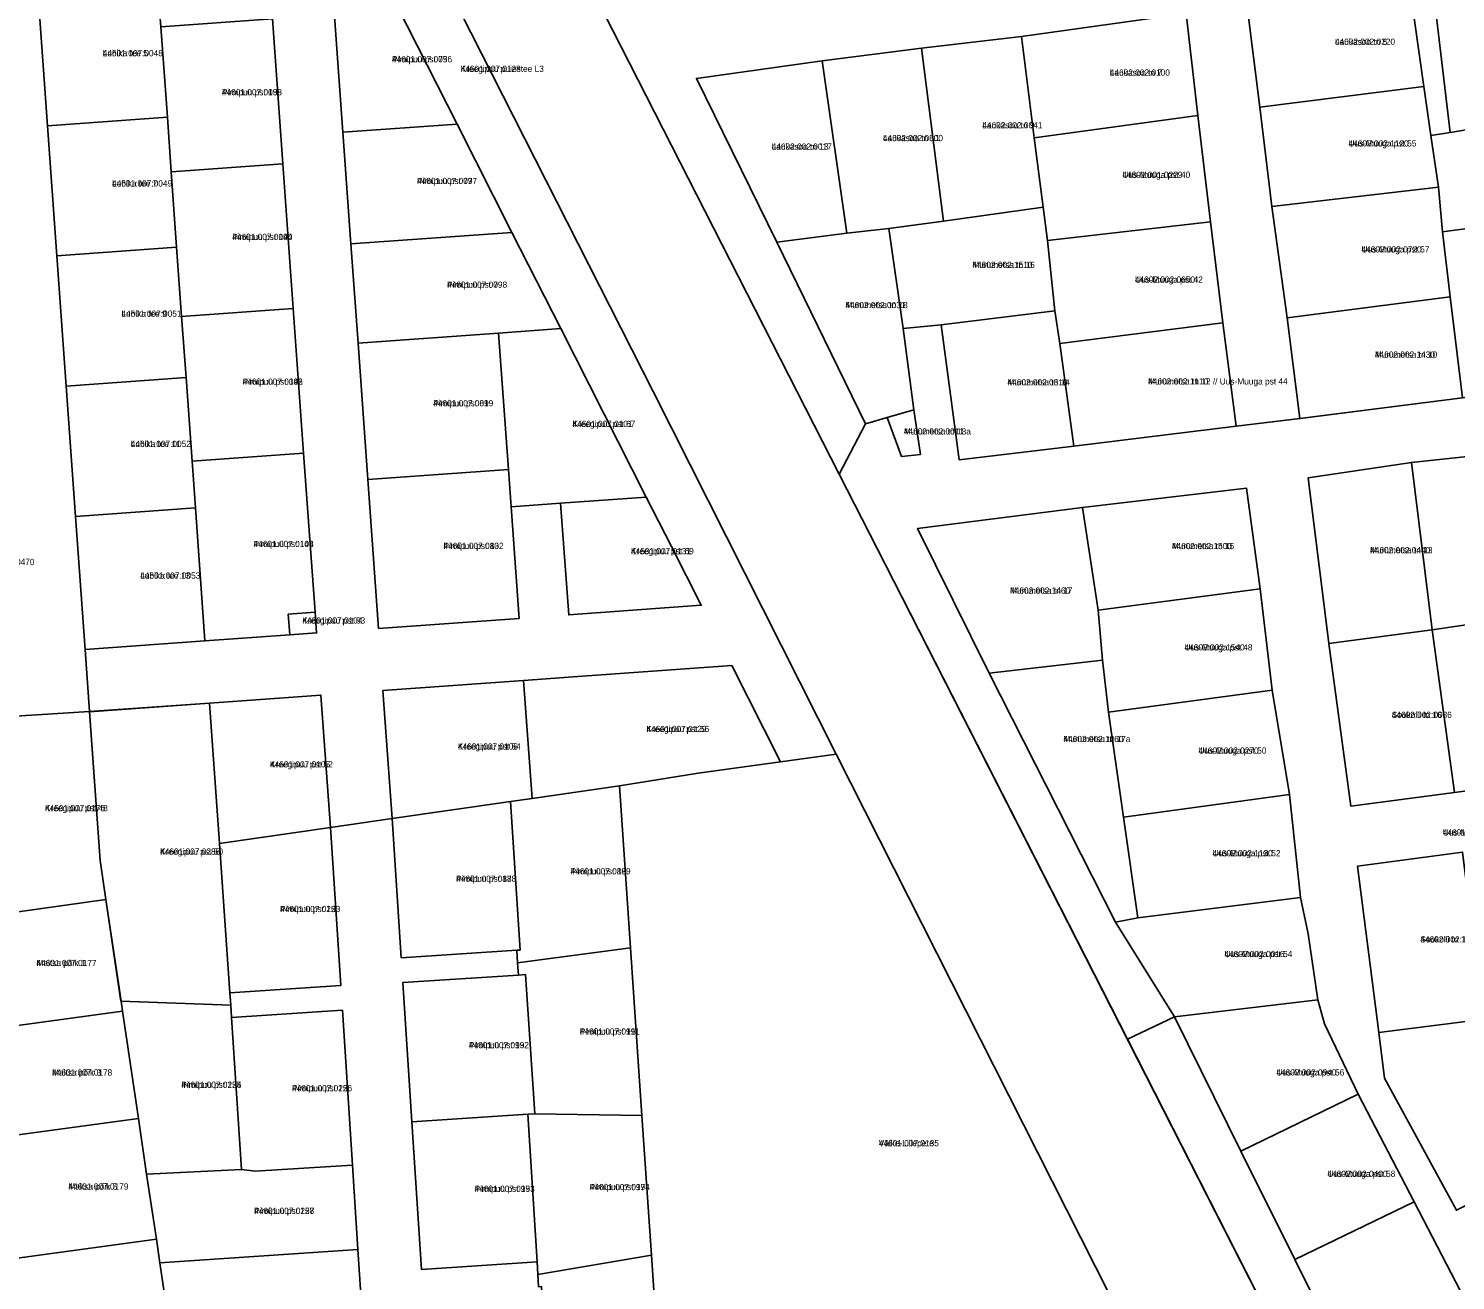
# Model space of a CAD drawing. Extents: x 551843 to 558501, y 6589003 to 6595718.
# Drawn here: x 554378.5 to 554722.9, y 6592914.1 to 6593216.1 of the extents above; entities that cross this region are included whole.
import ezdxf

# ---------------------------------------------------------------- set-up
doc = ezdxf.new("R2010")
doc.units = 0
for name, color, linetype in [('L_AADRESS', 7, 'Continuous'), ('PIIR', 7, 'Continuous'), ('TUNNUS', 7, 'Continuous')]:
    doc.layers.add(name, color=color, linetype=linetype)

msp = doc.modelspace()

# ---------------------------------------------------------------- linework, layer by layer
at = {"layer": 'PIIR'}
for points in [[(554923.69, 6592347.53), (554878.41, 6592438.09), (554841.8, 6592510.41), (554771.18, 6592649.95), (554642.95, 6592903.73), (554573.43, 6593041.09), (554529.22, 6593128.57), (554464.48, 6593256.08), (554446.62, 6593289.09), (554441.09, 6593299.31), (554261.19, 6593527.78)], [(554376.33, 6593286.93), (554378.58, 6593255.52), (554380.84, 6593224.1), (554383.09, 6593192.68), (554385.35, 6593161.26), (554387.61, 6593129.84), (554389.86, 6593098.42), (554392.17, 6593066.3), (554393.23, 6593051.33), (554367.77, 6593049.72)], [(554487.14, 6593279.28), (554574.16, 6593108.63), (554585.26, 6593086.87), (554696.4, 6592868.94), (554702.95, 6592872.25), (554722.28, 6592834.27), (554727.72, 6592823.94)], [(554672.53, 6593222.08), (554675.67, 6593197.16), (554678.52, 6593173.18), (554682.25, 6593146.32), (554685.32, 6593122.04), (554669.94, 6593120.21), (554666.74, 6593145.14), (554663.77, 6593169.5), (554660.66, 6593195.18), (554657.88, 6593219.71), (554618.16, 6593214.22), (554593.98, 6593211.35), (554570.07, 6593208.34), (554539.71, 6593204.1), (554559.11, 6593164.58), (554580.47, 6593120.73), (554574.16, 6593108.63), (554487.14, 6593279.28)], [(554464.48, 6593256.08), (554529.22, 6593128.57), (554573.43, 6593041.09), (554560.01, 6593039.24), (554548.22, 6593062.45), (554509.94, 6593059.7), (554497.97, 6593058.84), (554464.06, 6593056.41), (554466.27, 6593025.51), (554451.39, 6593023.38), (554449.1, 6593055.33), (554422.17, 6593053.4), (554393.23, 6593051.33), (554392.17, 6593066.3), (554421.09, 6593068.38), (554441.54, 6593069.85), (554448.02, 6593070.31), (554447.67, 6593075.3), (554444.91, 6593113.7), (554442.4, 6593148.61), (554439.89, 6593183.52), (554437.39, 6593218.43)], [(554717.27, 6593227.73), (554721.55, 6593191.06), (554716.94, 6593190.29), (554715.19, 6593202.16), (554711.65, 6593227.21)], [(554726.23, 6592907.32), (554712.86, 6592933.09), (554699.37, 6592959.06), (554691.24, 6592975.98), (554689.63, 6592981.77), (554687.32, 6592997.7), (554685.5, 6593006.52), (554682.81, 6593031.31), (554678.61, 6593056.51), (554675.75, 6593080.96), (554672.43, 6593105.25), (554632.84, 6593100.61), (554593.06, 6593095.54), (554610.31, 6593060.62), (554640.84, 6593000.52), (554655.06, 6592977.69), (554643.69, 6592972.29), (554585.26, 6593086.87), (554574.16, 6593108.63), (554580.47, 6593120.73), (554585.75, 6593122.26), (554589.15, 6593112.88), (554593.76, 6593113.38), (554592.18, 6593124.13), (554589.55, 6593143.72), (554598.77, 6593144.62), (554603.12, 6593112.07), (554630.79, 6593115.36), (554669.97, 6593120.21), (554685.35, 6593122.05), (554724.53, 6593127.05)], [(554736.93, 6593114.1), (554712.22, 6593111.46), (554687.3, 6593107.73), (554692.34, 6593067.78), (554697.58, 6593028.54), (554722.61, 6593031.83), (554747.33, 6593035.13)], [(554459.5, 6592898.77), (554458.02, 6592921.54), (554456.69, 6592941.94), (554454.26, 6592979.27), (554427.52, 6592977.52), (554427.33, 6592980.52), (554427.12, 6592983.51), (554453.87, 6592985.25), (554451.39, 6593023.38), (554466.27, 6593025.51), (554468.46, 6592991.94), (554496.35, 6592993.75), (554496.55, 6592990.76), (554496.75, 6592987.77), (554468.84, 6592985.98), (554471.03, 6592952.38), (554473.35, 6592916.76), (554501.28, 6592918.58), (554501.42, 6592915.58), (554501.57, 6592912.59)], [(554724.59, 6593017.45), (554699.24, 6593014.07), (554704.39, 6592973.93), (554705.77, 6592962.91), (554723.11, 6592931.04)], [(554723.65, 6592882.76), (554702.95, 6592872.25), (554696.4, 6592868.94), (554643.69, 6592972.29), (554655.06, 6592977.69), (554671.09, 6592945.33), (554684.09, 6592919.15), (554697.11, 6592892.89), (554701.82, 6592884.15), (554730.76, 6592898.25)]]:
    msp.add_lwpolyline(points, dxfattribs=at)
for points in [[(554450.52, 6593244.94), (554455.4, 6593245.29), (554481.92, 6593193.06), (554454.39, 6593191.08)], [(554455.4, 6593245.29), (554450.52, 6593244.94), (554454.39, 6593191.08), (554456.32, 6593164.15), (554458.04, 6593140.21), (554460.41, 6593107.3), (554462.99, 6593071.39), (554496.9, 6593073.82), (554494.96, 6593100.76), (554506.93, 6593101.61), (554508.87, 6593074.68), (554540.84, 6593076.98), (554533.65, 6593091.16), (554527.59, 6593103.1), (554506.96, 6593143.72), (554495.17, 6593166.94), (554481.92, 6593193.06)], [(554739.34, 6593230.36), (554743.04, 6593194.66), (554721.55, 6593191.06), (554717.27, 6593227.73)], [(554711.65, 6593227.21), (554715.19, 6593202.16), (554675.67, 6593197.16), (554672.53, 6593222.08)], [(554409.76, 6593226.17), (554410.46, 6593216.5), (554412.02, 6593194.75), (554383.09, 6593192.68), (554380.84, 6593224.1)], [(554657.88, 6593219.71), (554660.66, 6593195.18), (554621.17, 6593189.78), (554618.16, 6593214.22)], [(554412.96, 6593181.59), (554412.02, 6593194.75), (554410.46, 6593216.5), (554437.39, 6593218.43), (554439.89, 6593183.52)], [(554593.98, 6593211.35), (554618.16, 6593214.22), (554621.17, 6593189.78), (554623.38, 6593173.05), (554599.31, 6593169.67)], [(554593.98, 6593211.35), (554599.31, 6593169.67), (554586.11, 6593167.87), (554575.99, 6593166.75), (554570.07, 6593208.34)], [(554559.11, 6593164.58), (554539.71, 6593204.1), (554570.07, 6593208.34), (554575.99, 6593166.75)], [(554675.67, 6593197.16), (554715.19, 6593202.16), (554716.94, 6593190.29), (554718.76, 6593177.87), (554678.52, 6593173.18)], [(554412.02, 6593194.75), (554412.96, 6593181.59), (554414.27, 6593163.34), (554385.35, 6593161.26), (554383.09, 6593192.68)], [(554454.39, 6593191.08), (554481.92, 6593193.06), (554495.17, 6593166.94), (554456.32, 6593164.15)], [(554623.38, 6593173.05), (554621.17, 6593189.78), (554660.66, 6593195.18), (554663.77, 6593169.5), (554624.42, 6593165.01)], [(554718.76, 6593177.87), (554716.94, 6593190.29), (554721.55, 6593191.06), (554743.04, 6593194.66), (554748.83, 6593195.16), (554751.22, 6593171.39), (554746.86, 6593170.72), (554719.74, 6593167.11)], [(554412.96, 6593181.59), (554439.89, 6593183.52), (554442.4, 6593148.61), (554415.47, 6593146.68), (554414.27, 6593163.34)], [(554718.76, 6593177.87), (554719.74, 6593167.11), (554721.58, 6593151.37), (554682.25, 6593146.32), (554678.52, 6593173.18)], [(554589.55, 6593143.72), (554586.11, 6593167.87), (554599.31, 6593169.67), (554623.38, 6593173.05), (554624.42, 6593165.01), (554626.15, 6593148.01), (554598.74, 6593144.62)], [(554663.77, 6593169.5), (554666.74, 6593145.14), (554627.41, 6593140.15), (554626.15, 6593148.01), (554624.42, 6593165.01)], [(554746.86, 6593170.72), (554749.6, 6593130.9), (554724.53, 6593127.05), (554721.58, 6593151.37), (554719.74, 6593167.11)], [(554456.32, 6593164.15), (554495.17, 6593166.94), (554506.96, 6593143.72), (554491.96, 6593142.65), (554458.04, 6593140.21)], [(554589.55, 6593143.72), (554592.18, 6593124.13), (554585.75, 6593122.26), (554580.47, 6593120.73), (554559.11, 6593164.58), (554575.99, 6593166.75), (554586.11, 6593167.87)], [(554414.27, 6593163.34), (554415.47, 6593146.68), (554416.53, 6593131.92), (554387.61, 6593129.84), (554385.35, 6593161.26)], [(554724.53, 6593127.05), (554685.32, 6593122.04), (554682.25, 6593146.32), (554721.58, 6593151.37)], [(554415.47, 6593146.68), (554442.4, 6593148.61), (554444.91, 6593113.7), (554417.98, 6593111.77), (554416.53, 6593131.92)], [(554603.09, 6593112.07), (554598.74, 6593144.62), (554626.15, 6593148.01), (554627.41, 6593140.15), (554630.76, 6593115.36)], [(554666.74, 6593145.14), (554669.94, 6593120.21), (554630.76, 6593115.36), (554627.41, 6593140.15)], [(554458.04, 6593140.21), (554491.96, 6593142.65), (554494.32, 6593109.73), (554460.41, 6593107.3)], [(554491.96, 6593142.65), (554506.96, 6593143.72), (554527.59, 6593103.1), (554506.93, 6593101.61), (554494.96, 6593100.76), (554494.32, 6593109.73)], [(554416.53, 6593131.92), (554417.98, 6593111.77), (554418.79, 6593100.5), (554389.86, 6593098.42), (554387.61, 6593129.84)], [(554592.18, 6593124.13), (554593.76, 6593113.38), (554589.15, 6593112.88), (554585.75, 6593122.26)], [(554417.98, 6593111.77), (554444.91, 6593113.7), (554447.67, 6593075.3), (554441.18, 6593074.84), (554441.54, 6593069.85), (554421.09, 6593068.38), (554418.79, 6593100.5)], [(554717.24, 6593071.08), (554712.22, 6593111.46), (554736.93, 6593114.1), (554741.75, 6593074.71)], [(554460.41, 6593107.3), (554494.32, 6593109.73), (554494.96, 6593100.76), (554496.9, 6593073.82), (554462.99, 6593071.39)], [(554712.22, 6593111.46), (554717.24, 6593071.08), (554692.34, 6593067.78), (554687.3, 6593107.73)], [(554506.93, 6593101.61), (554527.59, 6593103.1), (554533.65, 6593091.16), (554540.84, 6593076.98), (554508.87, 6593074.68)], [(554675.75, 6593080.96), (554636.67, 6593075.81), (554632.84, 6593100.61), (554672.43, 6593105.25)], [(554418.79, 6593100.5), (554421.09, 6593068.38), (554392.17, 6593066.3), (554389.86, 6593098.42)], [(554610.31, 6593060.62), (554593.06, 6593095.54), (554632.84, 6593100.61), (554636.67, 6593075.81), (554637.69, 6593063.72)], [(554639.14, 6593051.21), (554637.69, 6593063.72), (554636.67, 6593075.81), (554675.75, 6593080.96), (554678.61, 6593056.51)], [(554448.02, 6593070.31), (554441.54, 6593069.85), (554441.18, 6593074.84), (554447.67, 6593075.3)], [(554741.75, 6593074.71), (554747.33, 6593035.13), (554722.61, 6593031.83), (554717.24, 6593071.08)], [(554692.34, 6593067.78), (554717.24, 6593071.08), (554722.61, 6593031.83), (554697.58, 6593028.54)], [(554497.97, 6593058.84), (554509.94, 6593059.7), (554548.22, 6593062.45), (554560.01, 6593039.24), (554540.12, 6593036.49), (554521.16, 6593033.4), (554500.02, 6593030.36)], [(554637.69, 6593063.72), (554639.14, 6593051.21), (554642.73, 6593025.86), (554646.19, 6593001.55), (554640.84, 6593000.52), (554610.31, 6593060.62)], [(554464.06, 6593056.41), (554497.97, 6593058.84), (554500.02, 6593030.36), (554494.82, 6593029.62), (554466.27, 6593025.51)], [(554422.17, 6593053.4), (554449.1, 6593055.33), (554451.39, 6593023.38), (554424.59, 6593019.54)], [(554678.61, 6593056.51), (554682.81, 6593031.31), (554642.73, 6593025.86), (554639.14, 6593051.21)], [(554367.77, 6593049.72), (554393.23, 6593051.33), (554395.81, 6593015.41), (554397.21, 6593005.99), (554370.76, 6593002.33)], [(554393.21, 6593051.28), (554422.19, 6593053.38), (554424.58, 6593019.5), (554427.14, 6592983.49), (554427.35, 6592980.55), (554400.83, 6592981.46), (554397.18, 6593005.97), (554395.79, 6593015.4)], [(554521.16, 6593033.4), (554540.12, 6593036.49), (554560.01, 6593039.24), (554573.43, 6593041.09), (554642.95, 6592903.73), (554646.24, 6592883.65), (554532.75, 6592862.8), (554531.22, 6592885.11), (554528.84, 6592920.17), (554526.55, 6592953.9), (554523.81, 6592994.34)], [(554494.82, 6593029.62), (554500.02, 6593030.36), (554521.16, 6593033.4), (554523.81, 6592994.34), (554496.55, 6592990.76), (554496.35, 6592993.75), (554497.15, 6592993.8)], [(554642.73, 6593025.86), (554682.81, 6593031.31), (554685.5, 6593006.52), (554646.19, 6593001.55)], [(554466.27, 6593025.51), (554494.82, 6593029.62), (554497.15, 6592993.8), (554496.35, 6592993.75), (554468.46, 6592991.94)], [(554424.59, 6593019.54), (554451.39, 6593023.38), (554453.87, 6592985.25), (554427.12, 6592983.51)], [(554699.24, 6593014.07), (554724.59, 6593017.45), (554729.51, 6592977.07), (554725.39, 6592976.58), (554704.39, 6592973.93)], [(554687.32, 6592997.7), (554689.63, 6592981.77), (554655.06, 6592977.69), (554640.84, 6593000.52), (554646.19, 6593001.55), (554685.5, 6593006.52)], [(554347.91, 6592999.22), (554370.76, 6593002.33), (554397.21, 6593005.99), (554400.85, 6592981.48), (554401.21, 6592979.08), (554363.49, 6592973.9), (554360.96, 6592992.34), (554349.04, 6592990.97)], [(554496.55, 6592990.76), (554523.81, 6592994.34), (554526.55, 6592953.9), (554500.72, 6592954.31), (554498.43, 6592987.91), (554496.75, 6592987.77)], [(554468.84, 6592985.98), (554496.75, 6592987.77), (554498.43, 6592987.91), (554500.72, 6592954.31), (554499.03, 6592954.2), (554471.03, 6592952.38)], [(554363.49, 6592973.9), (554401.21, 6592979.08), (554405.05, 6592953.2), (554367.05, 6592947.99)], [(554400.85, 6592981.48), (554427.33, 6592980.52), (554427.52, 6592977.52), (554429.91, 6592940.87), (554407.03, 6592939.78), (554405.05, 6592953.2), (554401.21, 6592979.08)], [(554427.52, 6592977.52), (554454.26, 6592979.27), (554456.69, 6592941.94), (554433.18, 6592940.44), (554429.91, 6592940.87)], [(554699.37, 6592959.06), (554671.09, 6592945.33), (554655.06, 6592977.69), (554689.63, 6592981.77), (554691.24, 6592975.98)], [(554725.39, 6592976.58), (554742.86, 6592941.04), (554723.11, 6592931.04), (554705.77, 6592962.91), (554704.39, 6592973.93)], [(554684.09, 6592919.15), (554671.09, 6592945.33), (554699.37, 6592959.06), (554712.86, 6592933.09)], [(554367.05, 6592947.99), (554405.05, 6592953.2), (554407.03, 6592939.78), (554409.37, 6592924.1), (554371.05, 6592918.84)], [(554471.03, 6592952.38), (554499.03, 6592954.2), (554501.28, 6592918.58), (554473.35, 6592916.76)], [(554499.03, 6592954.2), (554500.72, 6592954.31), (554526.55, 6592953.9), (554528.84, 6592920.17), (554501.42, 6592915.58), (554501.28, 6592918.58)], [(554407.03, 6592939.78), (554429.91, 6592940.87), (554433.18, 6592940.44), (554456.69, 6592941.94), (554458.02, 6592921.54), (554410.22, 6592918.36), (554409.37, 6592924.1)], [(554697.11, 6592892.89), (554684.09, 6592919.15), (554712.86, 6592933.09), (554726.23, 6592907.32), (554730.76, 6592898.25), (554701.82, 6592884.15)], [(554371.05, 6592918.84), (554409.37, 6592924.1), (554410.22, 6592918.36), (554413.54, 6592896.01), (554413.66, 6592895.25), (554375.02, 6592889.95)], [(554410.22, 6592918.36), (554458.02, 6592921.54), (554459.5, 6592898.77), (554413.54, 6592896.01)], [(554501.42, 6592915.58), (554528.84, 6592920.17), (554531.22, 6592885.11), (554506.03, 6592877.79), (554504.33, 6592877.68), (554502.32, 6592912.63), (554501.57, 6592912.59)]]:
    msp.add_lwpolyline(points, close=True, dxfattribs=at)

# ---------------------------------------------------------------- texts
at = {"layer": 'L_AADRESS'}
for s, p in [('Laukasoo tn 5', (554693.78, 6593212.19)), ('Lubika tee 5', (554396.43, 6593209.43)), ('Pirnipuu pst 75', (554466.22, 6593207.96)), ('Kreegipuu puiestee L3', (554482.8, 6593205.66)), ('Laukasoo tn 7', (554639.45, 6593204.75)), ('Pirnipuu pst 138', (554425.18, 6593200.01)), ('Laukasoo tn 9', (554608.68, 6593192.04)), ('Laukasoo tn 11', (554584.69, 6593188.95)), ('Uus-Muuga pst 55', (554697.06, 6593187.67)), ('Laukasoo tn 13', (554557.85, 6593186.89)), ('Lubika tee 7', (554398.68, 6593178.01)), ('Pirnipuu pst 77', (554472.27, 6593178.6)), ('Uus-Muuga pst 40', (554642.47, 6593180.1)), ('Pirnipuu pst 140', (554427.68, 6593165.1)), ('Uus-Muuga pst 57', (554700.19, 6593162.1)), ('Murumetsa tn 16', (554606.28, 6593158.38)), ('Pirnipuu pst 79', (554479.52, 6593153.58)), ('Uus-Muuga pst 42', (554645.51, 6593154.82)), ('Lubika tee 9', (554400.94, 6593146.59)), ('Murumetsa tn 18', (554575.64, 6593148.67)), ('Murumetsa tn 10', (554703.41, 6593136.71)), ('Pirnipuu pst 142', (554430.19, 6593130.19)), ('Murumetsa tn 14', (554614.75, 6593130.03)), ('Murumetsa tn 12 // Uus-Muuga pst 44', (554648.7, 6593130.25)), ('Pirnipuu pst 81', (554476.18, 6593124.98)), ('Kreegipuu pst 67', (554509.78, 6593120)), ('Murumetsa tn 18a', (554589.75, 6593118.19)), ('Lubika tee 11', (554403.2, 6593115.17)), ('Pirnipuu pst 144', (554432.82, 6593091.03)), ('Pirnipuu pst 83', (554478.65, 6593090.56)), ('Kreegipuu pst 69', (554523.89, 6593089.3)), ('Murumetsa tn 15', (554654.42, 6593090.53)), ('Murumetsa tn 13', (554702.27, 6593089.53)), ('Lubika tee 13', (554405.48, 6593083.4)), ('Murumetsa tn 17', (554615.38, 6593079.79)), ('Kreegipuu pst 63', (554444.6, 6593072.58)), ('Uus-Muuga pst 48', (554657.49, 6593066.09)), ('Sookolli tn 16', (554707.48, 6593049.81)), ('Kreegipuu pst 56', (554527.62, 6593046.4)), ('Murumetsa tn 17a', (554628.25, 6593043.98)), ('Kreegipuu pst 54', (554482.12, 6593042.18)), ('Uus-Muuga pst 50', (554660.86, 6593041.19)), ('Kreegipuu pst 52', (554436.78, 6593037.87)), ('Kreegipuu pst 48', (554382.49, 6593027.3)), ('Uus-Muuga puiestee L4', (554719.8, 6593021.44)), ('Kreegipuu pst 50', (554410.28, 6593016.83)), ('Uus-Muuga pst 52', (554664.25, 6593016.43)), ('Pirnipuu pst 89', (554509.32, 6593012.07)), ('Pirnipuu pst 87', (554481.71, 6593010.27)), ('Pirnipuu pst 150', (554439.23, 6593002.97)), ('Sookolli tn 15 // Uus-Muuga pst 65', (554714.38, 6592995.64)), ('Uus-Muuga pst 54', (554667.11, 6592992.11)), ('Maltsa põik 1', (554380.44, 6592989.94)), ('Pirnipuu pst 93', (554484.78, 6592970.14)), ('Pirnipuu pst 91', (554511.55, 6592973.43)), ('Maltsa põik 3', (554384.22, 6592963.53)), ('Uus-Muuga pst 56', (554679.64, 6592963.55)), ('Pirnipuu pst 154', (554415.38, 6592960.57)), ('Pirnipuu pst 156', (554442.11, 6592959.74)), ('Väike-Lillepere', (554583.7, 6592946.48)), ('Uus-Muuga pst 58', (554691.96, 6592939.1)), ('Maltsa põik 5', (554388.14, 6592936.02)), ('Pirnipuu pst 97', (554513.94, 6592935.89)), ('Pirnipuu pst 95', (554486.16, 6592935.48)), ('Pirnipuu pst 158', (554432.96, 6592930.15))]:
    msp.add_text(s, height=1.5, dxfattribs=at).set_placement(p)
at = {"layer": 'TUNNUS'}
for s, p in [('44602:002:0220', (554693.78, 6593212.19)), ('44601:007:0048', (554396.43, 6593209.43)), ('44601:007:0096', (554466.22, 6593207.96)), ('44601:007:0128', (554482.8, 6593205.66)), ('44602:002:0100', (554639.45, 6593204.75)), ('44601:007:0093', (554425.18, 6593200.01)), ('44602:002:0041', (554608.68, 6593192.04)), ('44602:002:0800', (554584.69, 6593188.95)), ('44602:002:1120', (554697.06, 6593187.67)), ('44602:002:0017', (554557.85, 6593186.89)), ('44601:007:0049', (554398.68, 6593178.01)), ('44601:007:0097', (554472.27, 6593178.6)), ('44601:001:0229', (554642.47, 6593180.1)), ('44601:007:0094', (554427.68, 6593165.1)), ('44602:002:0720', (554700.19, 6593162.1)), ('44602:002:1510', (554606.28, 6593158.38)), ('44601:007:0098', (554479.52, 6593153.58)), ('44602:002:0650', (554645.51, 6593154.82)), ('44601:007:0051', (554400.94, 6593146.59)), ('44602:002:0031', (554575.64, 6593148.67)), ('44602:002:1430', (554703.41, 6593136.71)), ('44601:007:0095', (554430.19, 6593130.19)), ('44602:002:0310', (554614.75, 6593130.03)), ('44602:002:1110', (554648.7, 6593130.25)), ('44601:007:0099', (554476.18, 6593124.98)), ('44601:007:0101', (554509.78, 6593120)), ('44602:002:0011', (554589.75, 6593118.19)), ('44601:007:0052', (554403.2, 6593115.17)), ('44601:007:0103', (554432.82, 6593091.03)), ('44601:007:0102', (554478.65, 6593090.56)), ('44601:007:0131', (554523.89, 6593089.3)), ('44602:002:1500', (554654.42, 6593090.53)), ('44602:002:0440', (554702.27, 6593089.53)), ('44601:007:0470', (554365.46, 6593086.7)), ('44601:007:0053', (554405.48, 6593083.4)), ('44602:002:1460', (554615.38, 6593079.79)), ('44601:007:0104', (554444.6, 6593072.58)), ('44602:002:1540', (554657.49, 6593066.09)), ('44602:002:0036', (554707.48, 6593049.81)), ('44601:007:0129', (554527.62, 6593046.4)), ('44602:002:1260', (554628.25, 6593043.98)), ('44601:007:0106', (554482.12, 6593042.18)), ('44602:002:0270', (554660.86, 6593041.19)), ('44601:007:0105', (554436.78, 6593037.87)), ('44601:007:0176', (554382.49, 6593027.3)), ('44601:001:0637', (554719.8, 6593021.44)), ('44601:007:0286', (554410.28, 6593016.83)), ('44602:002:1130', (554664.25, 6593016.43)), ('44601:007:0189', (554509.32, 6593012.07)), ('44601:007:0188', (554481.71, 6593010.27)), ('44601:007:0223', (554439.23, 6593002.97)), ('44602:002:1420', (554714.38, 6592995.64)), ('44602:002:0016', (554667.11, 6592992.11)), ('44601:007:0177', (554380.44, 6592989.94)), ('44601:007:0192', (554484.78, 6592970.14)), ('44601:007:0191', (554511.55, 6592973.43)), ('44601:007:0178', (554384.22, 6592963.53)), ('44602:002:0940', (554679.64, 6592963.55)), ('44601:007:0225', (554415.38, 6592960.57)), ('44601:007:0226', (554442.11, 6592959.74)), ('44601:007:0135', (554583.7, 6592946.48)), ('44602:002:0400', (554691.96, 6592939.1)), ('44601:007:0179', (554388.14, 6592936.02)), ('44601:007:0194', (554513.94, 6592935.89)), ('44601:007:0193', (554486.16, 6592935.48)), ('44601:007:0227', (554432.96, 6592930.15))]:
    msp.add_text(s, height=1.5, dxfattribs=at).set_placement(p)

doc.saveas('drawing.dxf')
